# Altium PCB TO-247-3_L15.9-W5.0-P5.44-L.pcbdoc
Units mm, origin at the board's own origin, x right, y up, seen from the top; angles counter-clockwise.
Board outline 28.66 x 18.32 mm, 2 copper layers (Top Layer, Bottom Layer), stack 0 mm thick; 1 components, 0 nets, 3 pads, 0 vias.
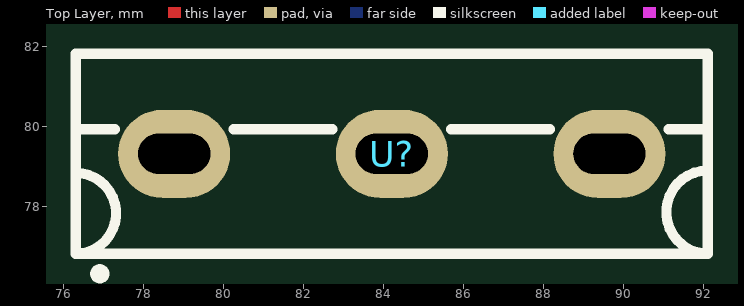
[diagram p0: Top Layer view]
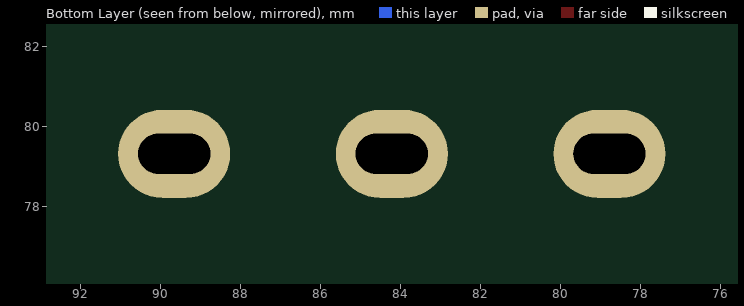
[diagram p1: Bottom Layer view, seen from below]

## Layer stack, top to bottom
Top Layer: signal copper (thickness not stored)
Bottom Layer: signal copper (thickness not stored)

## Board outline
98.51,69.85 69.85,69.85 69.85,88.17 98.51,88.17

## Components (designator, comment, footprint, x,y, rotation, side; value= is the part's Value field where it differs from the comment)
U? "" TO-247-3_L15.9-W5.0-P5.44-L 84.21,79.32 r0 top

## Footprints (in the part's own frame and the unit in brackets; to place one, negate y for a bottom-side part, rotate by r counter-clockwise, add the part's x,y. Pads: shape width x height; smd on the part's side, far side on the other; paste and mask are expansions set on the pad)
TO-247-3_L15.9-W5.0-P5.44-L [mm]
  oval 2.8x2.2 hole 1 slot 1.8 at 0 deg paste+0 mask+0.05: 1(-5.44,0) 2(0,0) 3(5.44,0)
  silkscreen extent -7.9,-3.12 7.9,2.5

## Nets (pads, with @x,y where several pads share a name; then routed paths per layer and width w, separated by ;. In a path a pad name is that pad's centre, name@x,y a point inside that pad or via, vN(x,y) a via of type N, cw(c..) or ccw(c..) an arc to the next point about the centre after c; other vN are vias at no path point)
pads on no net: U?.1 U?.2 U?.3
